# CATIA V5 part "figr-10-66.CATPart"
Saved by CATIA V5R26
Part number: Part1
Bounding box of the stored display mesh (mm): x -80.563 to 63.541, y -72 to 69, z -55 to 56
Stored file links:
  D:\_Deepak\CATIA\CATIA V5-6R2016_Deepak\Resources\Part files\Partfiles\c10_catia_v5_6r2016_prt\figr-10-66.CATPart
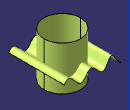
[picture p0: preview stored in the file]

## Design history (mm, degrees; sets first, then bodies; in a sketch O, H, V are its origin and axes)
Set1
  Sketch1 on xy-plane, origin (0, 0, 0), H (-1, 0, 0), V (0, -1, 0)
    circle A1 centre (0, 0) radius 45.985
  Extrude1: Element1 Sketch1, Lim1 56, Lim2 55, Direction xy-plane
  Sketch2 on zx-plane, origin (0, 0, 0), H (1, 0, 0), V (0, 0, -1)
    spline S1 through (-80.5635, 24.8913) (-73.6025, 19.8803) (-54.8525, -3.3629) (-35.1982, 19.8803) (-2.6271, -1.6506) (16.6996, 17.2854) (52.4104, -6.7877) (63.5409, 1.5862)
  Extrude2: Element1 Sketch2, Lim1 72, Lim2 69, Direction Sketch1.V
Body1 (main body)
